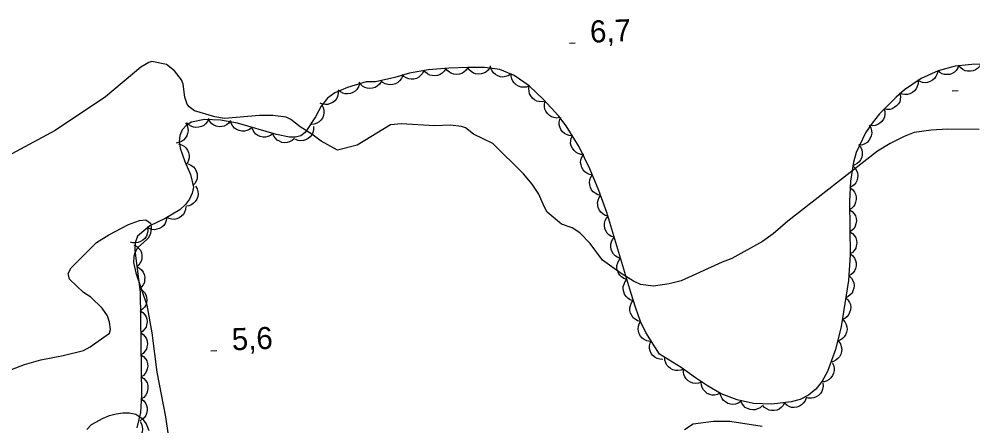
# Model space of a CAD drawing. Extents: x 336540 to 340074, y 5572036 to 5573747.
# Drawn here: x 337443.6 to 337573.5, y 5573040 to 5573095.4 of the extents above; entities that cross this region are included whole.
import ezdxf

# ---------------------------------------------------------------- set-up
doc = ezdxf.new("R2010")
doc.units = 0
for name, color, linetype in [('Niveau 2', 7, 'Continuous'), ('Niveau 3', 7, 'Continuous'), ('Niveau 44', 7, 'Continuous')]:
    doc.layers.add(name, color=color, linetype=linetype)

msp = doc.modelspace()

# ---------------------------------------------------------------- linework, layer by layer
at = {"layer": 'Niveau 2'}
for points in [[(337574.3, 5573080.32), (337569.99, 5573080.39), (337567.8, 5573080.27), (337565.48, 5573079.95), (337564.09, 5573079.4), (337562.19, 5573078.43), (337560.48, 5573077.41), (337548.25, 5573067.85), (337546.24, 5573066.13), (337544.8, 5573065.12), (337540.63, 5573062.8), (337539.32, 5573062.31), (337533.73, 5573059.75), (337532.09, 5573059.33), (337529.96, 5573059.03), (337528.17, 5573059.25), (337527.22, 5573059.69), (337525.54, 5573060.75), (337523.03, 5573062.58), (337521.32, 5573064.84), (337519.94, 5573066.29), (337518.87, 5573066.94), (337517.42, 5573067.46), (337515.5, 5573069.09), (337515.05, 5573069.87), (337514.35, 5573071.56), (337513.45, 5573072.92), (337512.26, 5573074.29), (337508.07, 5573078.43), (337505.44, 5573079.72), (337504.34, 5573080.58), (337503.79, 5573080.77), (337502.31, 5573080.92), (337500.18, 5573080.84), (337495.6, 5573081.13), (337494.13, 5573080.97), (337489.62, 5573078.22), (337486.92, 5573077.55), (337484.72, 5573078.75), (337483.44, 5573079.69), (337481.83, 5573080.72), (337480.59, 5573081.71), (337479.94, 5573082.04), (337478.11, 5573082.24), (337476.28, 5573082.25), (337471.54, 5573081.85), (337470.23, 5573082.06), (337467.45, 5573082.9), (337466.71, 5573083.42), (337466.47, 5573083.77), (337466.15, 5573084.76), (337465.92, 5573086.52), (337465.67, 5573087.11), (337464.71, 5573088.34), (337463.62, 5573089.2), (337461.65, 5573089.57), (337461.22, 5573089.47), (337460.13, 5573088.8), (337455.34, 5573084.78), (337448.48, 5573080.19), (337442.55, 5573077.01)], [(337441.94, 5573047.44), (337444.28, 5573048.35), (337446.5, 5573049), (337449.57, 5573049.6), (337452.33, 5573050.26), (337453.25, 5573050.77), (337455.86, 5573052.62), (337456, 5573053.13), (337455.89, 5573054.14), (337455.6, 5573055), (337454.88, 5573056.01), (337453.31, 5573057.52), (337452.31, 5573058.16), (337450.41, 5573059.97), (337450.26, 5573060.76), (337450.65, 5573061.5), (337454.09, 5573064.95), (337455.79, 5573066), (337458.44, 5573067.4), (337459.97, 5573067.95), (337460.83, 5573068.05), (337461.45, 5573067.58), (337461.56, 5573067.06), (337461.44, 5573066.18), (337461.17, 5573065.62), (337460.97, 5573065.38), (337459.67, 5573064.26), (337459.31, 5573063.55), (337459.17, 5573063.05), (337459.16, 5573062.24), (337459.44, 5573060.83), (337460.95, 5573056.46), (337461.62, 5573052.66), (337462.33, 5573047.34), (337463.51, 5573041.23), (337463.84, 5573038.73)], [(337452.77, 5573039.53), (337453.43, 5573040.22), (337454.99, 5573041.05), (337455.88, 5573041.41), (337456.77, 5573041.66), (337457.67, 5573041.79), (337458.57, 5573041.81), (337459.48, 5573041.61), (337460.28, 5573041.06), (337460.86, 5573040.29), (337461.22, 5573039.4)], [(337534.18, 5573039.52), (337535.35, 5573040.27), (337538.12, 5573040.66), (337540.36, 5573040.66), (337544.75, 5573039.98)]]:
    msp.add_lwpolyline(points, dxfattribs=at)
at = {"layer": 'Niveau 3'}
for p, q in [((337518.5, 5573092.07), (337519.3, 5573092.11)), ((337570.64, 5573085.61), (337571.45, 5573085.64)), ((337469.69, 5573050.21), (337470.49, 5573050.25))]:
    msp.add_line(p, q, dxfattribs=at)
at = {"layer": 'Niveau 44'}
for points in [[(337575.78, 5573089.26), (337573.34, 5573089.18), (337571.04, 5573088.96), (337568.73, 5573088.34), (337566.42, 5573087.27), (337564.13, 5573085.72), (337563, 5573084.73), (337560.75, 5573082.48), (337559.73, 5573081.22), (337558.84, 5573079.87), (337557.58, 5573077.21), (337557.2, 5573075.91), (337556.79, 5573073.29), (337556.66, 5573070.54), (337556.77, 5573063.3), (337556.51, 5573059.79), (337555.53, 5573053.53), (337554.76, 5573050.41), (337553.64, 5573047.41), (337552.93, 5573046.1), (337552.08, 5573045.03), (337551.07, 5573044.17), (337549.95, 5573043.61), (337548.72, 5573043.29), (337546.1, 5573042.96), (337543.56, 5573043.05), (337541.34, 5573043.54), (337539.2, 5573044.38), (337537.32, 5573045.44), (337535.66, 5573046.54), (337533.71, 5573047.97), (337530.79, 5573049.77), (337528.91, 5573052.73), (337528.21, 5573054.21), (337527.54, 5573056.01), (337526.87, 5573058.14), (337523.62, 5573069.06), (337522.52, 5573072.02), (337521.28, 5573074.97), (337519.85, 5573077.97), (337518.07, 5573080.85), (337517.05, 5573082.15), (337514.98, 5573084.42), (337513.01, 5573086.3), (337510.98, 5573087.69), (337509.02, 5573088.49), (337506.96, 5573088.76), (337504.68, 5573088.77), (337502.1, 5573088.67), (337499.32, 5573088.47), (337496.74, 5573088.01), (337494.73, 5573087.42), (337492.12, 5573086.83), (337490.84, 5573086.81), (337488.29, 5573086.05), (337486.58, 5573085.33), (337485.54, 5573084.6), (337484.69, 5573083.51), (337483.95, 5573082.08), (337482.51, 5573079.92), (337481.91, 5573079.48), (337481.2, 5573079.29), (337480.38, 5573079.28), (337478.62, 5573079.67), (337473.31, 5573081.18), (337470.99, 5573081.61), (337468.82, 5573081.71), (337467.03, 5573081.35), (337466.34, 5573080.91), (337465.78, 5573080.29), (337465.43, 5573079.52), (337465.38, 5573078.67), (337465.49, 5573077.78), (337466.11, 5573075.97), (337466.91, 5573074.2)], [(337498.68, 5573088.36), (337498.51, 5573087.97), (337498.25, 5573087.67), (337498, 5573087.45), (337497.68, 5573087.3), (337497.32, 5573087.2), (337496.94, 5573087.2), (337496.62, 5573087.23), (337496.29, 5573087.37), (337495.98, 5573087.57), (337495.73, 5573087.83)], [(337501.67, 5573088.64), (337501.46, 5573088.28), (337501.16, 5573088), (337500.89, 5573087.81), (337500.56, 5573087.69), (337500.19, 5573087.63), (337499.81, 5573087.67), (337499.49, 5573087.74), (337499.19, 5573087.91), (337498.9, 5573088.14), (337498.67, 5573088.42)], [(337504.66, 5573088.77), (337504.44, 5573088.41), (337504.14, 5573088.15), (337503.86, 5573087.96), (337503.52, 5573087.86), (337503.16, 5573087.81), (337502.78, 5573087.86), (337502.46, 5573087.94), (337502.16, 5573088.12), (337501.88, 5573088.36), (337501.66, 5573088.65)], [(337507.66, 5573088.76), (337507.43, 5573088.41), (337507.11, 5573088.16), (337506.83, 5573087.99), (337506.49, 5573087.9), (337506.12, 5573087.87), (337505.74, 5573087.93), (337505.43, 5573088.02), (337505.13, 5573088.22), (337504.86, 5573088.47), (337504.66, 5573088.77)], [(337510.52, 5573087.88), (337510.18, 5573087.64), (337509.79, 5573087.53), (337509.46, 5573087.47), (337509.11, 5573087.52), (337508.76, 5573087.63), (337508.43, 5573087.83), (337508.18, 5573088.03), (337507.98, 5573088.32), (337507.82, 5573088.66), (337507.75, 5573089.01)], [(337571.56, 5573089.1), (337571.43, 5573088.71), (337571.19, 5573088.38), (337570.96, 5573088.14), (337570.66, 5573087.96), (337570.31, 5573087.84), (337569.93, 5573087.8), (337569.6, 5573087.8), (337569.27, 5573087.91), (337568.94, 5573088.09), (337568.67, 5573088.32)], [(337574.57, 5573089.3), (337574.37, 5573088.93), (337574.08, 5573088.65), (337573.81, 5573088.45), (337573.48, 5573088.33), (337573.12, 5573088.26), (337572.74, 5573088.29), (337572.42, 5573088.34), (337572.1, 5573088.51), (337571.81, 5573088.73), (337571.58, 5573089.01)], [(337495.77, 5573087.66), (337495.62, 5573087.27), (337495.37, 5573086.95), (337495.13, 5573086.72), (337494.82, 5573086.55), (337494.47, 5573086.44), (337494.08, 5573086.42), (337493.76, 5573086.44), (337493.43, 5573086.56), (337493.11, 5573086.75), (337492.84, 5573086.99)], [(337513.05, 5573086.27), (337512.66, 5573086.12), (337512.26, 5573086.09), (337511.93, 5573086.1), (337511.59, 5573086.22), (337511.27, 5573086.4), (337511, 5573086.67), (337510.79, 5573086.92), (337510.65, 5573087.25), (337510.57, 5573087.61), (337510.57, 5573087.97)], [(337568.67, 5573088.31), (337568.6, 5573087.9), (337568.42, 5573087.54), (337568.24, 5573087.26), (337567.97, 5573087.04), (337567.65, 5573086.85), (337567.28, 5573086.75), (337566.96, 5573086.7), (337566.61, 5573086.75), (337566.26, 5573086.87), (337565.95, 5573087.05)], [(337489.9, 5573086.53), (337489.78, 5573086.13), (337489.55, 5573085.8), (337489.33, 5573085.55), (337489.03, 5573085.37), (337488.68, 5573085.23), (337488.3, 5573085.19), (337487.98, 5573085.18), (337487.64, 5573085.28), (337487.31, 5573085.45), (337487.03, 5573085.67)], [(337492.86, 5573086.84), (337492.63, 5573086.49), (337492.32, 5573086.23), (337492.04, 5573086.05), (337491.7, 5573085.96), (337491.34, 5573085.92), (337490.96, 5573085.98), (337490.64, 5573086.06), (337490.35, 5573086.25), (337490.07, 5573086.5), (337489.86, 5573086.79)], [(337515.21, 5573084.2), (337514.81, 5573084.11), (337514.4, 5573084.14), (337514.08, 5573084.21), (337513.77, 5573084.38), (337513.48, 5573084.61), (337513.25, 5573084.92), (337513.09, 5573085.2), (337513.01, 5573085.54), (337512.98, 5573085.91), (337513.04, 5573086.27)], [(337565.99, 5573086.98), (337565.99, 5573086.56), (337565.87, 5573086.17), (337565.73, 5573085.87), (337565.5, 5573085.61), (337565.22, 5573085.37), (337564.87, 5573085.21), (337564.56, 5573085.11), (337564.21, 5573085.11), (337563.84, 5573085.16), (337563.51, 5573085.3)], [(337487.02, 5573085.64), (337487.03, 5573085.22), (337486.92, 5573084.83), (337486.79, 5573084.53), (337486.56, 5573084.26), (337486.28, 5573084.02), (337485.93, 5573083.86), (337485.62, 5573083.75), (337485.27, 5573083.74), (337484.9, 5573083.79), (337484.57, 5573083.92)], [(337563.53, 5573085.26), (337563.61, 5573084.85), (337563.57, 5573084.44), (337563.49, 5573084.12), (337563.31, 5573083.82), (337563.07, 5573083.54), (337562.76, 5573083.31), (337562.48, 5573083.15), (337562.13, 5573083.08), (337561.76, 5573083.07), (337561.41, 5573083.14)], [(337484.78, 5573083.68), (337484.98, 5573083.31), (337485.06, 5573082.92), (337485.08, 5573082.59), (337485.01, 5573082.24), (337484.87, 5573081.9), (337484.64, 5573081.6), (337484.41, 5573081.36), (337484.11, 5573081.18), (337483.76, 5573081.06), (337483.4, 5573081.02)], [(337517.22, 5573081.96), (337516.81, 5573081.9), (337516.4, 5573081.96), (337516.09, 5573082.06), (337515.79, 5573082.25), (337515.52, 5573082.5), (337515.31, 5573082.82), (337515.17, 5573083.11), (337515.11, 5573083.46), (337515.11, 5573083.83), (337515.2, 5573084.18)], [(337561.34, 5573083.2), (337561.46, 5573082.8), (337561.46, 5573082.4), (337561.41, 5573082.07), (337561.27, 5573081.75), (337561.06, 5573081.44), (337560.78, 5573081.19), (337560.51, 5573081), (337560.17, 5573080.89), (337559.81, 5573080.84), (337559.45, 5573080.87)], [(337518.91, 5573079.49), (337518.49, 5573079.51), (337518.11, 5573079.64), (337517.82, 5573079.79), (337517.56, 5573080.03), (337517.34, 5573080.33), (337517.2, 5573080.68), (337517.1, 5573081), (337517.12, 5573081.35), (337517.19, 5573081.71), (337517.33, 5573082.04)], [(337466.21, 5573081.23), (337466.43, 5573080.87), (337466.53, 5573080.48), (337466.57, 5573080.15), (337466.51, 5573079.81), (337466.39, 5573079.46), (337466.17, 5573079.14), (337465.96, 5573078.89), (337465.66, 5573078.7), (337465.32, 5573078.56), (337464.97, 5573078.5)], [(337469.36, 5573081.82), (337469.2, 5573081.43), (337468.94, 5573081.12), (337468.7, 5573080.9), (337468.38, 5573080.74), (337468.03, 5573080.64), (337467.65, 5573080.63), (337467.32, 5573080.65), (337466.99, 5573080.78), (337466.68, 5573080.98), (337466.42, 5573081.23)], [(337472.37, 5573081.55), (337472.12, 5573081.21), (337471.79, 5573080.97), (337471.5, 5573080.81), (337471.16, 5573080.74), (337470.79, 5573080.72), (337470.41, 5573080.8), (337470.1, 5573080.91), (337469.82, 5573081.11), (337469.56, 5573081.38), (337469.37, 5573081.68)], [(337475.25, 5573080.63), (337474.93, 5573080.36), (337474.56, 5573080.2), (337474.24, 5573080.11), (337473.89, 5573080.12), (337473.53, 5573080.19), (337473.18, 5573080.35), (337472.9, 5573080.52), (337472.67, 5573080.79), (337472.48, 5573081.11), (337472.37, 5573081.45)], [(337478.14, 5573079.81), (337477.82, 5573079.54), (337477.45, 5573079.38), (337477.13, 5573079.29), (337476.78, 5573079.3), (337476.41, 5573079.37), (337476.07, 5573079.53), (337475.79, 5573079.7), (337475.56, 5573079.97), (337475.37, 5573080.29), (337475.25, 5573080.63)], [(337483.64, 5573080.75), (337483.65, 5573080.33), (337483.55, 5573079.94), (337483.42, 5573079.63), (337483.2, 5573079.36), (337482.93, 5573079.11), (337482.58, 5573078.94), (337482.28, 5573078.83), (337481.93, 5573078.81), (337481.56, 5573078.85), (337481.22, 5573078.97)], [(337559.34, 5573080.93), (337559.55, 5573080.57), (337559.65, 5573080.17), (337559.68, 5573079.84), (337559.62, 5573079.5), (337559.49, 5573079.15), (337559.27, 5573078.84), (337559.06, 5573078.59), (337558.76, 5573078.41), (337558.41, 5573078.27), (337558.06, 5573078.21)], [(337481.06, 5573079.13), (337480.76, 5573078.84), (337480.39, 5573078.66), (337480.08, 5573078.55), (337479.73, 5573078.54), (337479.36, 5573078.59), (337479.01, 5573078.73), (337478.72, 5573078.89), (337478.48, 5573079.14), (337478.26, 5573079.44), (337478.13, 5573079.78)], [(337520.49, 5573076.94), (337520.07, 5573076.95), (337519.69, 5573077.09), (337519.39, 5573077.24), (337519.14, 5573077.48), (337518.92, 5573077.78), (337518.77, 5573078.13), (337518.68, 5573078.44), (337518.69, 5573078.8), (337518.76, 5573079.16), (337518.91, 5573079.49)], [(337465.29, 5573078.37), (337465.69, 5573078.26), (337466.03, 5573078.05), (337466.29, 5573077.84), (337466.48, 5573077.54), (337466.63, 5573077.21), (337466.7, 5573076.83), (337466.71, 5573076.5), (337466.63, 5573076.16), (337466.48, 5573075.82), (337466.26, 5573075.53)], [(337557.89, 5573078.28), (337558.16, 5573077.96), (337558.32, 5573077.58), (337558.4, 5573077.26), (337558.39, 5573076.91), (337558.32, 5573076.55), (337558.15, 5573076.2), (337557.98, 5573075.93), (337557.71, 5573075.7), (337557.39, 5573075.51), (337557.05, 5573075.4)], [(337521.66, 5573074.17), (337521.25, 5573074.23), (337520.88, 5573074.4), (337520.61, 5573074.58), (337520.38, 5573074.85), (337520.19, 5573075.17), (337520.09, 5573075.54), (337520.03, 5573075.86), (337520.08, 5573076.21), (337520.19, 5573076.56), (337520.37, 5573076.87)], [(337466.58, 5573075.65), (337466.97, 5573075.49), (337467.29, 5573075.24), (337467.52, 5573075), (337467.68, 5573074.69), (337467.8, 5573074.34), (337467.82, 5573073.96), (337467.8, 5573073.63), (337467.68, 5573073.3), (337467.49, 5573072.98), (337467.24, 5573072.72)], [(337557.12, 5573075.38), (337557.42, 5573075.1), (337557.63, 5573074.75), (337557.75, 5573074.44), (337557.79, 5573074.09), (337557.76, 5573073.72), (337557.64, 5573073.36), (337557.51, 5573073.06), (337557.27, 5573072.8), (337556.98, 5573072.57), (337556.65, 5573072.42)], [(337466.91, 5573074.2), (337467.29, 5573072.51), (337467.14, 5573071.67), (337466.78, 5573070.88), (337466.23, 5573070.13), (337465.46, 5573069.4), (337463.45, 5573068.24), (337461.35, 5573067.21), (337459.69, 5573065.83), (337459.38, 5573064.92), (337459.3, 5573063.87), (337460.04, 5573058.2), (337460.23, 5573044.25), (337460.09, 5573041.84), (337459.61, 5573039.75)], [(337522.79, 5573071.38), (337522.38, 5573071.46), (337522.02, 5573071.66), (337521.75, 5573071.85), (337521.54, 5573072.13), (337521.37, 5573072.46), (337521.28, 5573072.83), (337521.24, 5573073.15), (337521.3, 5573073.5), (337521.43, 5573073.85), (337521.63, 5573074.15)], [(337467.58, 5573072.64), (337467.8, 5573072.28), (337467.9, 5573071.89), (337467.94, 5573071.56), (337467.88, 5573071.22), (337467.76, 5573070.87), (337467.54, 5573070.55), (337467.33, 5573070.3), (337467.04, 5573070.11), (337466.69, 5573069.97), (337466.34, 5573069.91)], [(337556.75, 5573072.41), (337557.08, 5573072.16), (337557.32, 5573071.83), (337557.48, 5573071.54), (337557.56, 5573071.2), (337557.57, 5573070.83), (337557.49, 5573070.45), (337557.39, 5573070.14), (337557.18, 5573069.86), (337556.91, 5573069.6), (337556.61, 5573069.41)], [(337523.81, 5573068.56), (337523.4, 5573068.66), (337523.05, 5573068.87), (337522.79, 5573069.07), (337522.59, 5573069.36), (337522.43, 5573069.69), (337522.36, 5573070.07), (337522.33, 5573070.39), (337522.41, 5573070.74), (337522.55, 5573071.08), (337522.76, 5573071.37)], [(337466.26, 5573069.86), (337466.23, 5573069.45), (337466.09, 5573069.07), (337465.93, 5573068.78), (337465.68, 5573068.53), (337465.38, 5573068.32), (337465.02, 5573068.18), (337464.7, 5573068.1), (337464.35, 5573068.12), (337463.99, 5573068.21), (337463.66, 5573068.36)], [(337556.68, 5573069.41), (337557.03, 5573069.18), (337557.29, 5573068.87), (337557.46, 5573068.59), (337557.56, 5573068.25), (337557.6, 5573067.89), (337557.54, 5573067.51), (337557.45, 5573067.19), (337557.27, 5573066.89), (337557.02, 5573066.62), (337556.72, 5573066.41)], [(337463.67, 5573068.35), (337463.61, 5573067.94), (337463.44, 5573067.57), (337463.27, 5573067.29), (337463, 5573067.06), (337462.68, 5573066.87), (337462.32, 5573066.76), (337462, 5573066.7), (337461.65, 5573066.74), (337461.29, 5573066.85), (337460.98, 5573067.03)], [(337524.63, 5573065.67), (337524.23, 5573065.8), (337523.89, 5573066.03), (337523.65, 5573066.25), (337523.47, 5573066.55), (337523.33, 5573066.89), (337523.28, 5573067.27), (337523.28, 5573067.6), (337523.38, 5573067.94), (337523.54, 5573068.27), (337523.77, 5573068.55)], [(337461.03, 5573066.95), (337461.07, 5573066.53), (337460.99, 5573066.13), (337460.89, 5573065.82), (337460.68, 5573065.53), (337460.42, 5573065.27), (337460.09, 5573065.08), (337459.79, 5573064.95), (337459.44, 5573064.91), (337459.07, 5573064.93), (337458.72, 5573065.03)], [(337556.72, 5573066.41), (337557.07, 5573066.18), (337557.33, 5573065.87), (337557.51, 5573065.59), (337557.6, 5573065.25), (337557.64, 5573064.89), (337557.58, 5573064.51), (337557.5, 5573064.19), (337557.31, 5573063.89), (337557.06, 5573063.62), (337556.77, 5573063.41)], [(337525.48, 5573062.8), (337525.09, 5573062.92), (337524.75, 5573063.15), (337524.5, 5573063.37), (337524.32, 5573063.68), (337524.19, 5573064.02), (337524.14, 5573064.4), (337524.13, 5573064.73), (337524.24, 5573065.06), (337524.4, 5573065.39), (337524.63, 5573065.67)], [(337459.2, 5573064.62), (337459.58, 5573064.44), (337459.87, 5573064.16), (337460.08, 5573063.9), (337460.21, 5573063.57), (337460.29, 5573063.21), (337460.27, 5573062.83), (337460.23, 5573062.51), (337460.07, 5573062.19), (337459.86, 5573061.89), (337459.59, 5573061.65)], [(337526.34, 5573059.92), (337525.94, 5573060.05), (337525.61, 5573060.28), (337525.36, 5573060.5), (337525.18, 5573060.8), (337525.04, 5573061.14), (337524.99, 5573061.52), (337524.99, 5573061.85), (337525.09, 5573062.19), (337525.26, 5573062.52), (337525.48, 5573062.8)], [(337556.78, 5573063.41), (337557.11, 5573063.15), (337557.34, 5573062.82), (337557.49, 5573062.52), (337557.55, 5573062.18), (337557.56, 5573061.81), (337557.47, 5573061.44), (337557.36, 5573061.13), (337557.14, 5573060.85), (337556.87, 5573060.6), (337556.56, 5573060.42)], [(337459.59, 5573061.65), (337459.96, 5573061.46), (337460.26, 5573061.18), (337460.47, 5573060.92), (337460.6, 5573060.6), (337460.68, 5573060.24), (337460.66, 5573059.85), (337460.62, 5573059.53), (337460.46, 5573059.21), (337460.25, 5573058.91), (337459.98, 5573058.67)], [(337527.2, 5573057.05), (337526.8, 5573057.17), (337526.46, 5573057.4), (337526.22, 5573057.62), (337526.03, 5573057.92), (337525.9, 5573058.27), (337525.85, 5573058.65), (337525.85, 5573058.97), (337525.95, 5573059.31), (337526.11, 5573059.64), (337526.34, 5573059.92)], [(337556.61, 5573060.41), (337556.91, 5573060.13), (337557.12, 5573059.78), (337557.24, 5573059.47), (337557.28, 5573059.12), (337557.25, 5573058.75), (337557.13, 5573058.39), (337557, 5573058.09), (337556.76, 5573057.83), (337556.47, 5573057.6), (337556.14, 5573057.45)], [(337460.03, 5573058.68), (337460.38, 5573058.45), (337460.64, 5573058.14), (337460.82, 5573057.86), (337460.91, 5573057.52), (337460.95, 5573057.15), (337460.89, 5573056.77), (337460.81, 5573056.46), (337460.62, 5573056.16), (337460.37, 5573055.88), (337460.07, 5573055.68)], [(337556.14, 5573057.45), (337556.45, 5573057.17), (337556.65, 5573056.81), (337556.78, 5573056.51), (337556.82, 5573056.16), (337556.79, 5573055.79), (337556.67, 5573055.43), (337556.53, 5573055.13), (337556.3, 5573054.87), (337556.01, 5573054.64), (337555.68, 5573054.49)], [(337528.21, 5573054.22), (337527.8, 5573054.32), (337527.45, 5573054.53), (337527.19, 5573054.73), (337526.99, 5573055.02), (337526.83, 5573055.35), (337526.76, 5573055.73), (337526.73, 5573056.06), (337526.81, 5573056.4), (337526.95, 5573056.74), (337527.16, 5573057.03)], [(337460.07, 5573055.68), (337460.42, 5573055.45), (337460.68, 5573055.14), (337460.86, 5573054.86), (337460.95, 5573054.52), (337460.99, 5573054.15), (337460.93, 5573053.77), (337460.85, 5573053.46), (337460.66, 5573053.16), (337460.41, 5573052.88), (337460.12, 5573052.68)], [(337529.49, 5573051.51), (337529.07, 5573051.57), (337528.71, 5573051.75), (337528.43, 5573051.93), (337528.2, 5573052.2), (337528.02, 5573052.52), (337527.91, 5573052.89), (337527.86, 5573053.21), (337527.91, 5573053.56), (337528.02, 5573053.91), (337528.2, 5573054.22)], [(337555.76, 5573054.47), (337556.04, 5573054.16), (337556.21, 5573053.79), (337556.31, 5573053.48), (337556.32, 5573053.12), (337556.26, 5573052.76), (337556.11, 5573052.41), (337555.95, 5573052.12), (337555.69, 5573051.89), (337555.38, 5573051.68), (337555.04, 5573051.56)], [(337460.12, 5573052.68), (337460.46, 5573052.45), (337460.72, 5573052.14), (337460.9, 5573051.86), (337461, 5573051.52), (337461.03, 5573051.15), (337460.97, 5573050.77), (337460.89, 5573050.46), (337460.7, 5573050.16), (337460.45, 5573049.88), (337460.16, 5573049.68)], [(337531.24, 5573049.06), (337530.82, 5573049.07), (337530.44, 5573049.2), (337530.14, 5573049.35), (337529.88, 5573049.58), (337529.66, 5573049.88), (337529.51, 5573050.23), (337529.42, 5573050.54), (337529.42, 5573050.9), (337529.49, 5573051.26), (337529.63, 5573051.59)], [(337555.17, 5573051.52), (337555.42, 5573051.18), (337555.54, 5573050.79), (337555.61, 5573050.47), (337555.57, 5573050.12), (337555.47, 5573049.76), (337555.28, 5573049.43), (337555.09, 5573049.17), (337554.8, 5573048.96), (337554.47, 5573048.79), (337554.12, 5573048.71)], [(337460.16, 5573049.68), (337460.51, 5573049.45), (337460.77, 5573049.14), (337460.94, 5573048.86), (337461.04, 5573048.52), (337461.07, 5573048.15), (337461.01, 5573047.77), (337460.93, 5573047.46), (337460.74, 5573047.16), (337460.49, 5573046.88), (337460.2, 5573046.68)], [(337534.06, 5573047.75), (337533.68, 5573047.58), (337533.28, 5573047.53), (337532.95, 5573047.53), (337532.61, 5573047.63), (337532.28, 5573047.8), (337531.99, 5573048.05), (337531.77, 5573048.29), (337531.62, 5573048.61), (337531.52, 5573048.97), (337531.51, 5573049.33)], [(337554.3, 5573048.63), (337554.49, 5573048.26), (337554.57, 5573047.86), (337554.58, 5573047.53), (337554.5, 5573047.18), (337554.35, 5573046.85), (337554.12, 5573046.54), (337553.89, 5573046.31), (337553.58, 5573046.14), (337553.23, 5573046.02), (337552.87, 5573045.99)], [(337536.46, 5573045.95), (337536.07, 5573045.81), (337535.66, 5573045.79), (337535.33, 5573045.82), (337535.01, 5573045.95), (337534.69, 5573046.14), (337534.42, 5573046.42), (337534.22, 5573046.67), (337534.1, 5573047), (337534.03, 5573047.37), (337534.04, 5573047.73)], [(337460.2, 5573046.68), (337460.55, 5573046.45), (337460.81, 5573046.14), (337460.98, 5573045.86), (337461.08, 5573045.52), (337461.11, 5573045.15), (337461.05, 5573044.77), (337460.97, 5573044.46), (337460.78, 5573044.16), (337460.53, 5573043.88), (337460.24, 5573043.68)], [(337539.06, 5573044.46), (337538.69, 5573044.27), (337538.29, 5573044.2), (337537.96, 5573044.19), (337537.62, 5573044.28), (337537.28, 5573044.43), (337536.99, 5573044.67), (337536.75, 5573044.9), (337536.59, 5573045.22), (337536.48, 5573045.57), (337536.45, 5573045.93)], [(337553.02, 5573045.83), (337553.07, 5573045.42), (337553, 5573045.02), (337552.89, 5573044.71), (337552.69, 5573044.42), (337552.43, 5573044.15), (337552.1, 5573043.96), (337551.81, 5573043.82), (337551.46, 5573043.78), (337551.09, 5573043.79), (337550.74, 5573043.89)], [(337541.85, 5573043.34), (337541.5, 5573043.1), (337541.12, 5573042.98), (337540.79, 5573042.92), (337540.44, 5573042.96), (337540.09, 5573043.07), (337539.76, 5573043.27), (337539.5, 5573043.46), (337539.3, 5573043.75), (337539.13, 5573044.09), (337539.06, 5573044.44)], [(337460.2, 5573043.68), (337460.53, 5573043.43), (337460.77, 5573043.1), (337460.92, 5573042.8), (337460.99, 5573042.46), (337461, 5573042.09), (337460.92, 5573041.72), (337460.81, 5573041.41), (337460.6, 5573041.13), (337460.33, 5573040.87), (337460.02, 5573040.68)], [(337544.8, 5573042.78), (337544.5, 5573042.49), (337544.14, 5573042.31), (337543.82, 5573042.2), (337543.47, 5573042.18), (337543.11, 5573042.23), (337542.75, 5573042.38), (337542.46, 5573042.53), (337542.22, 5573042.78), (337542.01, 5573043.09), (337541.87, 5573043.42)], [(337547.82, 5573043.18), (337547.63, 5573042.8), (337547.35, 5573042.51), (337547.09, 5573042.3), (337546.76, 5573042.17), (337546.4, 5573042.09), (337546.02, 5573042.11), (337545.7, 5573042.16), (337545.38, 5573042.31), (337545.08, 5573042.53), (337544.84, 5573042.8)], [(337550.74, 5573043.82), (337550.6, 5573043.42), (337550.36, 5573043.1), (337550.13, 5573042.86), (337549.83, 5573042.68), (337549.48, 5573042.56), (337549.1, 5573042.53), (337548.77, 5573042.53), (337548.44, 5573042.65), (337548.11, 5573042.82), (337547.84, 5573043.06)], [(337460.05, 5573040.63), (337460.25, 5573040.27), (337460.34, 5573039.88), (337460.37, 5573039.55), (337460.3, 5573039.2), (337460.17, 5573038.86), (337459.94, 5573038.55), (337459.73, 5573038.3), (337459.42, 5573038.13), (337459.07, 5573037.99), (337458.72, 5573037.95)]]:
    msp.add_lwpolyline(points, dxfattribs=at)

# ---------------------------------------------------------------- texts
at = {"layer": 'Niveau 3'}
for s, p in [('6,7    ', (337521.37, 5573092.15)), ('5,6    ', (337472.58, 5573050.29))]:
    msp.add_text(s, height=3, rotation=2.2763, dxfattribs=at).set_placement(p)

doc.saveas('drawing.dxf')
